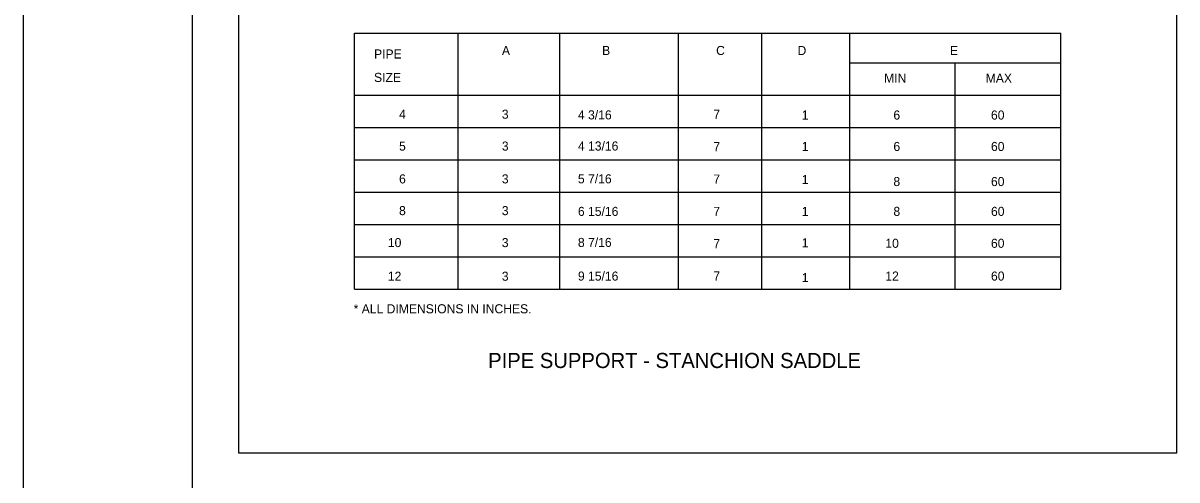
# Model space of a CAD drawing. Extents: x 2147138 to 2147698, y 2147153 to 2147515.
# Drawn here: x 2147137.8 to 2147290.5, y 2147347.7 to 2147408.1 of the extents above; entities that cross this region are included whole.
import ezdxf

# ---------------------------------------------------------------- set-up
doc = ezdxf.new("R2010")
doc.units = 0
for name, color, linetype in [('CONSTRUCTION_CLASS', 7, 'Continuous'), ('G-ANNO-TITL', 7, 'Continuous'), ('G-DETL-ANNO-LW10', 7, 'Continuous'), ('PATTERN_CLASS', 7, 'Continuous')]:
    doc.layers.add(name, color=color, linetype=linetype)

msp = doc.modelspace()

# ---------------------------------------------------------------- linework, layer by layer
for p, q in [((2147181.65, 2147398.6), (2147181.65, 2147406.81)), ((2147181.65, 2147406.81), (2147275.12, 2147406.81)), ((2147195.36, 2147398.6), (2147195.36, 2147406.81)), ((2147208.8, 2147398.6), (2147208.8, 2147406.81)), ((2147224.5, 2147398.6), (2147224.5, 2147406.81)), ((2147235.54, 2147398.6), (2147235.54, 2147406.81)), ((2147247.18, 2147398.6), (2147247.18, 2147406.81)), ((2147275.12, 2147398.6), (2147275.12, 2147406.81)), ((2147247.18, 2147402.88), (2147275.12, 2147402.88)), ((2147261.15, 2147398.6), (2147261.15, 2147402.88)), ((2147181.65, 2147398.6), (2147275.12, 2147398.6)), ((2147181.65, 2147398.6), (2147275.12, 2147398.6)), ((2147181.65, 2147372.93), (2147181.65, 2147398.6)), ((2147195.36, 2147372.93), (2147195.36, 2147398.6)), ((2147208.8, 2147372.93), (2147208.8, 2147398.6)), ((2147224.5, 2147372.93), (2147224.5, 2147398.6)), ((2147235.54, 2147372.93), (2147235.54, 2147398.6)), ((2147247.18, 2147372.93), (2147247.18, 2147398.6)), ((2147261.15, 2147372.93), (2147261.15, 2147398.6)), ((2147275.12, 2147372.93), (2147275.12, 2147398.6)), ((2147181.65, 2147394.32), (2147275.12, 2147394.32)), ((2147181.65, 2147390.04), (2147275.12, 2147390.04)), ((2147181.65, 2147385.77), (2147275.12, 2147385.77)), ((2147181.65, 2147381.49), (2147275.12, 2147381.49)), ((2147181.65, 2147377.21), (2147275.12, 2147377.21)), ((2147181.65, 2147372.93), (2147275.12, 2147372.93))]:
    msp.add_line(p, q)
at = {"layer": 'CONSTRUCTION_CLASS'}
for p, q in [((2147137.79, 2147515.08), (2147137.79, 2147152.81)), ((2147160.2, 2147160.52), (2147160.2, 2147507.94))]:
    msp.add_line(p, q, dxfattribs=at)
at = {"layer": 'PATTERN_CLASS'}
for p, q in [((2147166.29, 2147503.54), (2147166.29, 2147351.27)), ((2147290.48, 2147351.27), (2147290.48, 2147503.54)), ((2147166.29, 2147351.27), (2147290.48, 2147351.27)), ((2147166.29, 2147351.27), (2147166.29, 2147351.27))]:
    msp.add_line(p, q, dxfattribs=at)

# ---------------------------------------------------------------- texts
at = {"layer": 'G-ANNO-TITL'}
msp.add_text('PIPE SUPPORT - STANCHION SADDLE', height=2, dxfattribs=at).set_placement((2147199.33, 2147362.5))
at = {"layer": 'G-DETL-ANNO-LW10'}
for s, p in [('PIPE', (2147184.23, 2147403.46)), ('A', (2147201.15, 2147403.92)), ('B', (2147214.41, 2147403.92)), ('C', (2147229.5, 2147403.92)), ('D', (2147240.27, 2147403.92)), ('E', (2147260.43, 2147403.92)), ('SIZE', (2147184.23, 2147400.36)), ('MIN', (2147251.73, 2147400.26)), ('MAX', (2147265.17, 2147400.26)), ('4', (2147187.54, 2147395.49)), ('3', (2147201.14, 2147395.49)), ('4 3/16', (2147211.21, 2147395.4)), ('7', (2147229.13, 2147395.47)), ('1', (2147240.83, 2147395.38)), ('6', (2147252.96, 2147395.38)), ('60', (2147265.87, 2147395.38)), ('5', (2147187.54, 2147391.27)), ('3', (2147201.14, 2147391.27)), ('4 13/16', (2147211.21, 2147391.28)), ('7', (2147229.13, 2147391.19)), ('1', (2147240.83, 2147391.22)), ('6', (2147252.96, 2147391.22)), ('60', (2147265.87, 2147391.22)), ('6', (2147187.54, 2147386.93)), ('3', (2147201.14, 2147386.93)), ('5 7/16', (2147211.21, 2147386.94)), ('7', (2147229.13, 2147386.91)), ('1', (2147240.83, 2147386.84)), ('8', (2147252.96, 2147386.58)), ('60', (2147265.87, 2147386.58)), ('8', (2147187.54, 2147382.73)), ('3', (2147201.14, 2147382.73)), ('6 15/16', (2147211.21, 2147382.63)), ('7', (2147229.13, 2147382.63)), ('1', (2147240.83, 2147382.63)), ('8', (2147252.96, 2147382.63)), ('60', (2147265.87, 2147382.63)), ('8 7/16', (2147211.21, 2147378.52)), ('10', (2147186.06, 2147378.5)), ('3', (2147201.14, 2147378.5)), ('7', (2147229.13, 2147378.36)), ('1', (2147240.83, 2147378.48)), ('10', (2147251.89, 2147378.41)), ('60', (2147265.87, 2147378.41)), ('12', (2147186.06, 2147374.05)), ('3', (2147201.14, 2147374.05)), ('9 15/16', (2147211.21, 2147374.07)), ('7', (2147229.13, 2147374.08)), ('12', (2147251.89, 2147374.07)), ('60', (2147265.87, 2147374.07)), ('1', (2147240.83, 2147373.87)), ('* ALL DIMENSIONS IN INCHES.', (2147181.53, 2147369.74))]:
    msp.add_text(s, height=1.2, dxfattribs=at).set_placement(p)

doc.saveas('drawing.dxf')
